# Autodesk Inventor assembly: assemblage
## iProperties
Shininess: 41.0
Angle Display Precision: 2
Document Length Units: 11269
Document Angle Units: 11279
Document Time Units: 11290
Document Mass Units: 11283
Document Length Units Precision: 3
Document Angle Units Precision: 2
Compacted: True
Created: 2002-04
Part Number: assemblage
Document SubType Name: Assemblage
Designer: thchene
Density: 0.0
Volumn: 0.0
Area: 0.0
PropertySet Name: Model Information
Control State: 0
Master: False
Checked Out: False
Author: thchene
